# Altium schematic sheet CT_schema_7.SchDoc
size 277 x 170 mm
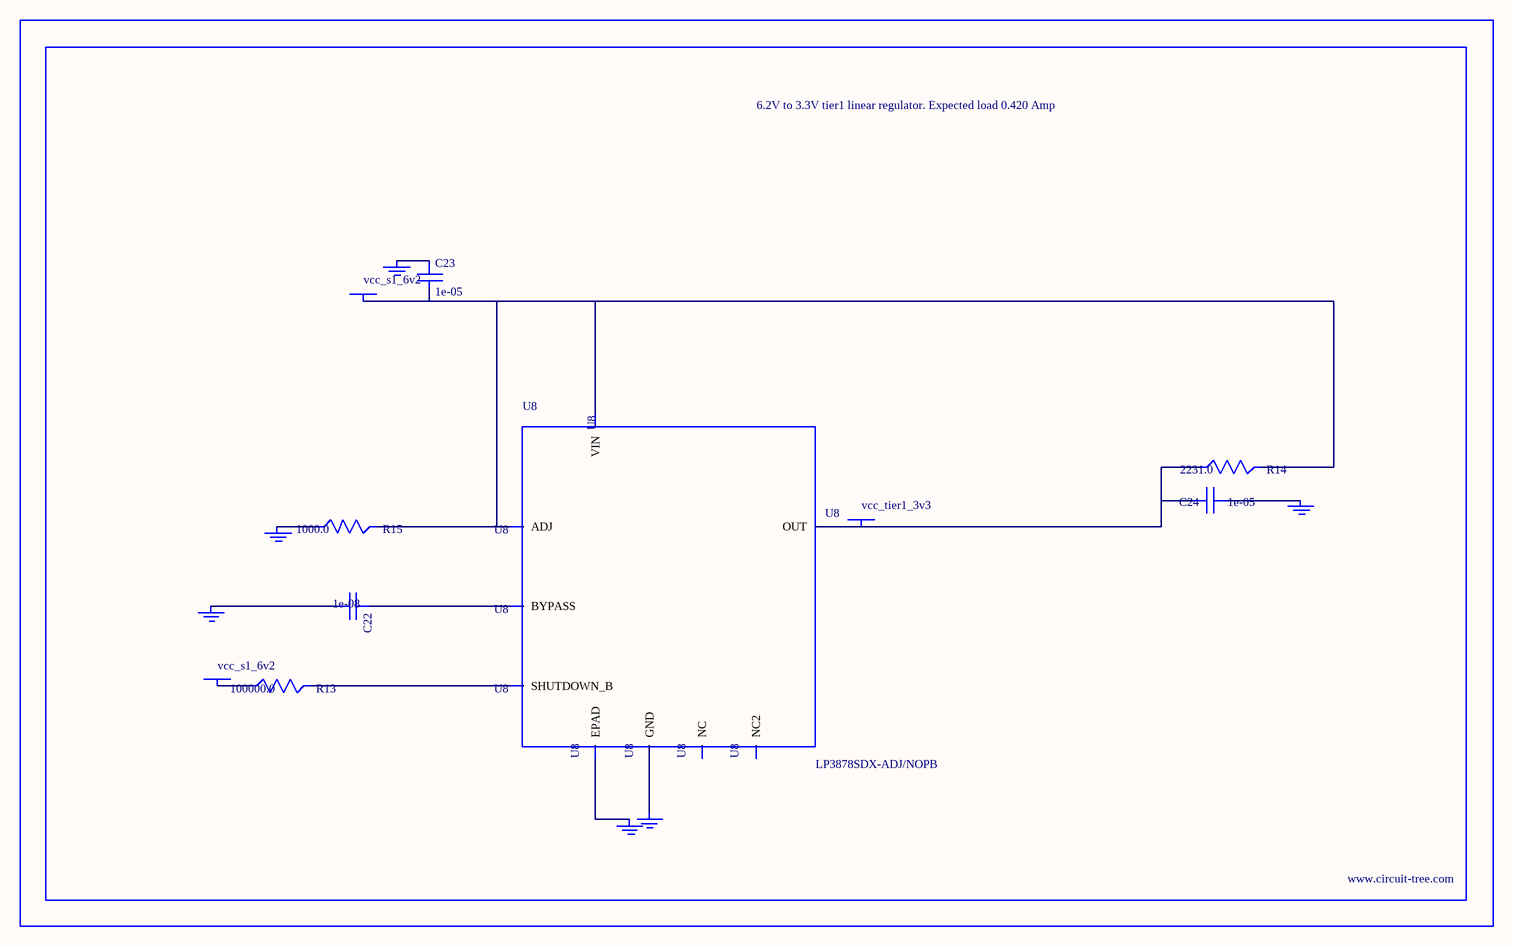
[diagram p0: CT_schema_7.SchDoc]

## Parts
BORDER6  (no value)
C22  1e-08  [C0402]
C23  1e-05  [C1206]
C24  1e-05  [C1210]
GND_INSTANCE_6_0  (no value)
GND_INSTANCE_6_1  (no value)
GND_INSTANCE_6_2  (no value)
GND_INSTANCE_6_3  (no value)
GND_INSTANCE_6_4  (no value)
GND_INSTANCE_6_5  (no value)
POWER_INSTANCE_6_0  vcc_s1_6v2
POWER_INSTANCE_6_1  vcc_s1_6v2
POWER_INSTANCE_6_2  vcc_tier1_3v3
R13  100000.0  [R0603]
R14  2231.0  [R0603]
R15  1000.0  [R0603]
U8  LP3878SDX-ADJ/NOPB  [WSON-8]

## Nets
NetC22_1: C22.1 U8.1(BYPASS)
NetC22_2: C22.2 GND_INSTANCE_6_0.0(GND)
NetC23_1: C23.1 GND_INSTANCE_6_1.0(GND)
NetC23_2: C23.2 POWER_INSTANCE_6_0.0(PWR) R14.2 R15.2 U8.4(VIN) U8.6(ADJ)
NetC24_1: C24.1 GND_INSTANCE_6_2.0(GND)
NetC24_2: C24.2 POWER_INSTANCE_6_2.0(PWR) R14.1 U8.5(OUT)
NetGND_INSTANCE_6_3_0: GND_INSTANCE_6_3.0(GND) R15.1
NetGND_INSTANCE_6_4_0: GND_INSTANCE_6_4.0(GND) U8.PAD(EPAD)
NetGND_INSTANCE_6_5_0: GND_INSTANCE_6_5.0(GND) U8.3(GND)
NetPOWER_INSTANCE_6_1_0: POWER_INSTANCE_6_1.0(PWR) R13.1
NetR13_2: R13.2 U8.8(SHUTDOWN_B)

Not connected (* = marked no-connect by the designer): U8 2(NC) 7(NC2)

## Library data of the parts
BORDER6 = BORDER_PAGE6
C22 = C0402C103K3RAC
C23 = C1206C106K3RACTU
C24 = GRM32DR61E106MA12L
GND_INSTANCE_6_0-GND_INSTANCE_6_5 = GND
POWER_INSTANCE_6_0-POWER_INSTANCE_6_2 = PWR
R13 = RC0603JR-07100KL
R14 = R14
R15 = RC0603JR-071KL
